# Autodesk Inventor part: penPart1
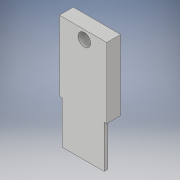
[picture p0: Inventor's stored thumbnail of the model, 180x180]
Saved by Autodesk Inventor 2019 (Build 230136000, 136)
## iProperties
Created: 2018-05
Part Number: penPart1
Material: Generic
Document SubType Name: Modeling
Designer: maste
Density: 1 g/cm^3
Appearance: Default
Part Number: penPart1_3DPrint
Author: maste
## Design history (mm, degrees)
sketch "Sketch1"
  geometry: L1 (-5.926, 5.482)-(5.074, 5.482); L2 (5.074, 5.482)-(5.074, -19.518); L3 (5.074, -19.518)-(-5.926, -19.518); L4 (-5.926, -19.518)-(-5.926, 5.482); 1 further point
  constraints: 8 end point, 2 parallel, 1 horizontal, 1 perpendicular
  dimensions: "d0" = 11 distance of L1.start L1.end; "d1" = 25 distance of L3.end L1.start
extrude "Extrusion1" new body sketch "Sketch1" distance "d2" = 1; taper "d3" = 0 deg
sketch "Sketch5"
  geometry: L1 (-6.475, -8.032)-(5.525, -8.032); L2 (5.525, -8.032)-(5.525, 10.856); L3 (5.525, 10.856)-(-6.475, 10.856); L4 (-6.475, 10.856)-(-6.475, -8.032); 1 further point
  constraints: 8 end point, 2 parallel, 1 horizontal, 1 perpendicular
  dimensions: "d4" = 12 distance of L2.end L3.end
extrude "Extrusion2" new body sketch "Sketch5" distance "d5" = 2; taper "d6" = 0 deg
combine "Combine1"
node "3D Sketch4"
node "3D Sketch5"
node "Direct Edit1"
node "Direct Edit2"
combine "Combine2"
  body "Solid2"
node "Direct Edit3"
node "Direct Edit4"
node "Direct Edit5"
sketch "Sketch6"
  geometry: 2 further points
hole "Hole1" sketch "Sketch6" at (6.022, 16.535) diameter "d34" = 3.4; stored, may be unused: countersink angle "d38" = 90 deg, drill point angle "d40" = 118 deg; dims "d35" = 3.708, "d36" = 6.3, "d37" = 2, "d39" = 10.65
node "Direct Edit6"
node "Direct Edit7"
body "Solid1"
move_body "Move1" dims "d9" = 1
move_body "Move2" dims "d12" = -1
move_body "Move3" dims "d15" = -0.25
move_body "Move4" dims "d18" = -0.25
move_body "Move5" dims "d21" = 0.25
move_body "Move6" dims "d24" = 0.25
move_body "Move7" dims "d27" = -0.5
move_body "Move8" dims "d30" = 0.5
move_body "Move9" dims "d33" = -0.25
move_body "Move10" dims "d43" = -0.25
move_body "Move11" dims "d46" = 0.25
move_body "Move12" dims "d49" = -0.25
move_body "Move13" dims "d52" = 0.25
move_body "Move14" dims "d55" = 0.25
other parameters: "sa_0" = 4, "d7" = 0, "d8" = 0, "d10" = 0, "d11" = 0, "d13" = 0, "d14" = 0, "d16" = 0, "d17" = 0, "d19" = 0, "d20" = 0, "d22" = 0, "d23" = 0, "d25" = 0, "d26" = 0, "d28" = 0, "d29" = 0, "d31" = 0, "d32" = 0, "d41" = 0, "d42" = 0, "d44" = 0, "d45" = 0, "d47" = 0, "d48" = 0, "d50" = 0, "d51" = 0, "d53" = 0, "d54" = 0
